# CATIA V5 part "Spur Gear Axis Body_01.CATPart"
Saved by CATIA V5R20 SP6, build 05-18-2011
Part number: Spur Gear Axis Body_01
Bounding box of the stored display mesh (mm): x 0 to 42, y -10 to 10, z -10 to 10
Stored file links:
  E:\#01 CATIA Lecture Materials\#06 DMU\#10 Kinematics Joints\#002 Gear Joint(Spur Gear)\Spur Gear Axis Body_01.CATPart
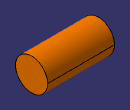
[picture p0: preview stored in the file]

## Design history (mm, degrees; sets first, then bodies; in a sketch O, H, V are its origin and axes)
Set1 "Reference Data"
  Point1 "Center Point": (0, 0, 0)
Body1 (main body)
  Sketch1 on yz-plane, origin (0, 0, 0), H (0, 1, 0), V (0, 0, 1)
    circle A1 centre (0, 0) radius 10
    radius A1 = 10
  Pad1: profile Sketch1, direction (1, 0, 0), length 42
